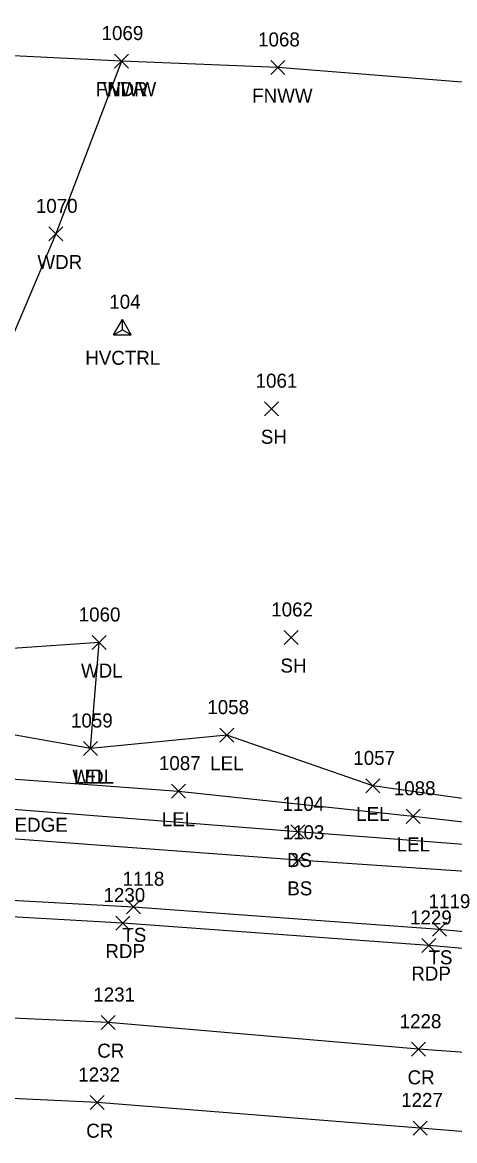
# Model space of a CAD drawing. Extents: x 1629176 to 1637209, y 606063 to 610167.
# Drawn here: x 1629302.4 to 1629364, y 607056.5 to 607215.9 of the extents above; entities that cross this region are included whole.
import ezdxf

# ---------------------------------------------------------------- set-up
doc = ezdxf.new("R2010")
doc.units = 0
for name, color, linetype in [('C_A', 7, 'Continuous'), ('C_C', 7, 'Continuous'), ('C_I', 7, 'Continuous'), ('CPSM', 7, 'Continuous'), ('L_A', 7, 'Continuous'), ('L_I', 7, 'Continuous'), ('L_TIC', 7, 'Continuous'), ('LARO', 7, 'Continuous'), ('LAWA', 7, 'Continuous'), ('LELB', 7, 'Continuous'), ('LFNC', 7, 'Continuous'), ('P_A', 7, 'Continuous'), ('P_I', 7, 'Continuous'), ('P_TIC', 7, 'Continuous'), ('PET', 7, 'Continuous'), ('PRC', 7, 'Continuous')]:
    doc.layers.add(name, color=color, linetype=linetype)

msp = doc.modelspace()

# ---------------------------------------------------------------- linework, layer by layer
at = {"layer": 'CPSM'}
for p, q in [((1629315.4, 607171.35), (1629316.65, 607173.51)), ((1629317.9, 607171.35), (1629316.65, 607173.51)), ((1629316.65, 607172.07), (1629316.65, 607173.51)), ((1629315.4, 607171.35), (1629316.65, 607172.07)), ((1629315.4, 607171.35), (1629317.9, 607171.35)), ((1629316.65, 607172.07), (1629316.65, 607172.07)), ((1629316.65, 607172.07), (1629317.9, 607171.35))]:
    msp.add_line(p, q, dxfattribs=at)
at = {"layer": 'L_TIC'}
for points in [[(1629315.51, 607209.37), (1629317.51, 607211.37)], [(1629317.51, 607209.37), (1629315.51, 607211.37)], [(1629315.51, 607209.37), (1629317.51, 607211.37)], [(1629317.51, 607209.37), (1629315.51, 607211.37)], [(1629337.82, 607208.46), (1629339.82, 607210.46)], [(1629339.82, 607208.46), (1629337.82, 607210.46)], [(1629306.16, 607184.73), (1629308.16, 607186.73)], [(1629308.16, 607184.73), (1629306.16, 607186.73)], [(1629336.9, 607159.81), (1629338.9, 607161.81)], [(1629338.9, 607159.81), (1629336.9, 607161.81)], [(1629312.32, 607126.48), (1629314.32, 607128.48)], [(1629314.32, 607126.48), (1629312.32, 607128.48)], [(1629339.7, 607127.19), (1629341.7, 607129.19)], [(1629341.7, 607127.19), (1629339.7, 607129.19)], [(1629330.53, 607113.27), (1629332.53, 607115.27)], [(1629332.53, 607113.27), (1629330.53, 607115.27)], [(1629311.1, 607111.36), (1629313.1, 607113.36)], [(1629313.1, 607111.36), (1629311.1, 607113.36)], [(1629311.1, 607111.36), (1629313.1, 607113.36)], [(1629313.1, 607111.36), (1629311.1, 607113.36)], [(1629323.64, 607105.29), (1629325.64, 607107.29)], [(1629325.64, 607105.29), (1629323.64, 607107.29)], [(1629351.35, 607106.03), (1629353.35, 607108.03)], [(1629353.35, 607106.03), (1629351.35, 607108.03)], [(1629357.13, 607101.7), (1629359.13, 607103.7)], [(1629359.13, 607101.7), (1629357.13, 607103.7)], [(1629340.68, 607099.48), (1629342.68, 607101.48)], [(1629342.68, 607099.48), (1629340.68, 607101.48)], [(1629340.71, 607095.43), (1629342.71, 607097.43)], [(1629342.71, 607095.43), (1629340.71, 607097.43)], [(1629317.24, 607088.8), (1629319.24, 607090.8)], [(1629319.24, 607088.8), (1629317.24, 607090.8)], [(1629360.89, 607085.6), (1629362.89, 607087.6)], [(1629362.89, 607085.6), (1629360.89, 607087.6)]]:
    msp.add_lwpolyline(points, dxfattribs=at)
at = {"layer": 'LARO'}
msp.add_lwpolyline([(1629525.56, 607097.75), (1629515.16, 607097.62), (1629496.01, 607097.55), (1629454.84, 607100.2), (1629419.24, 607105.4), (1629419.23, 607105.4), (1629378.86, 607107.73), (1629367.09, 607104.98), (1629352.35, 607107.03), (1629331.53, 607114.27), (1629312.1, 607112.36), (1629284.4, 607117.27), (1629264.96, 607112.44), (1629237.03, 607114.71), (1629236.02, 607111.12), (1629264.43, 607110.11), (1629291.77, 607108.71), (1629324.64, 607106.29), (1629358.13, 607102.7), (1629389.76, 607099.17), (1629430.17, 607097.09), (1629468.65, 607094.42), (1629506.63, 607093.09)], dxfattribs=at)
at = {"layer": 'LAWA'}
for points in [[(1629316.51, 607210.37), (1629307.16, 607185.73), (1629298.62, 607165.66), (1629261.38, 607160.41), (1629253.01, 607164.91), (1629257.91, 607184.79), (1629269.2, 607213.11)], [(1629312.1, 607112.36), (1629313.32, 607127.48), (1629283.07, 607125.37), (1629264.34, 607119.92), (1629237.03, 607114.71)]]:
    msp.add_lwpolyline(points, dxfattribs=at)
at = {"layer": 'LELB'}
for points in [[(1629624.92, 607174.61), (1629622.69, 607143.68), (1629611.35, 607114.32), (1629581.53, 607116.51), (1629566.42, 607115.03), (1629550.74, 607095.26), (1629545.75, 607082.85), (1629510.01, 607084.74), (1629471.96, 607087.97), (1629425.24, 607093.21), (1629387.71, 607096.98), (1629341.68, 607100.48), (1629296.79, 607103.99), (1629252.13, 607105.67), (1629240.26, 607107.21), (1629209.02, 607107.58), (1629183.53, 607109.94)], [(1629683.15, 607057.43), (1629646, 607061.54), (1629600.81, 607070.68), (1629551.82, 607076.32), (1629509.64, 607081.4), (1629471.16, 607085.48), (1629425.18, 607090.24), (1629387.34, 607093.37), (1629341.71, 607096.43), (1629295.02, 607099.94), (1629251.22, 607103.28), (1629239.88, 607103.86), (1629208.74, 607106), (1629183.2, 607107.98)], [(1629182.81, 607095.71), (1629228.31, 607094.18), (1629271.2, 607092.37), (1629318.24, 607089.8), (1629361.89, 607086.6), (1629408.03, 607082.19), (1629449.64, 607077.67), (1629495.68, 607072.1), (1629543.77, 607066.01), (1629589.78, 607058.79)]]:
    msp.add_lwpolyline(points, dxfattribs=at)
at = {"layer": 'LFNC'}
msp.add_lwpolyline([(1629584.57, 607180.8), (1629561.91, 607184.66), (1629527.04, 607188.99), (1629501.6, 607191.75), (1629445.35, 607199.37), (1629407.21, 607203.61), (1629374.06, 607206.64), (1629338.82, 607209.46), (1629316.51, 607210.37), (1629282.73, 607212.04), (1629269.2, 607213.11), (1629248.99, 607214.08), (1629210.8, 607215.89), (1629190.17, 607214.66)], dxfattribs=at)
at = {"layer": 'P_TIC'}
for points in [[(1629315.73, 607086.48), (1629317.73, 607088.48)], [(1629317.73, 607086.48), (1629315.73, 607088.48)], [(1629359.37, 607083.28), (1629361.37, 607085.28)], [(1629361.37, 607083.28), (1629359.37, 607085.28)], [(1629313.63, 607072.29), (1629315.63, 607074.29)], [(1629315.63, 607072.29), (1629313.63, 607074.29)], [(1629357.89, 607068.49), (1629359.89, 607070.49)], [(1629359.89, 607068.49), (1629357.89, 607070.49)], [(1629312.06, 607060.88), (1629314.06, 607062.88)], [(1629314.06, 607060.88), (1629312.06, 607062.88)], [(1629358.1, 607057.26), (1629360.1, 607059.26)], [(1629360.1, 607057.26), (1629358.1, 607059.26)]]:
    msp.add_lwpolyline(points, dxfattribs=at)
at = {"layer": 'PET'}
msp.add_lwpolyline([(1630115.59, 606918.47), (1630070.26, 606934.37), (1630047.19, 606942.61), (1630027.81, 606949.5), (1629999.64, 606958.79), (1629963.88, 606969.73), (1629916.37, 606983.66), (1629883.8, 606991.87), (1629841.7, 607003.38), (1629794.53, 607014.94), (1629751.13, 607024.85), (1629703.98, 607035.26), (1629666.74, 607043.02), (1629621.43, 607051.04), (1629588.28, 607056.93), (1629542.89, 607063.67), (1629493.94, 607070.34), (1629447.94, 607075.86), (1629406.53, 607080.22), (1629360.37, 607084.28), (1629316.73, 607087.48), (1629269.81, 607090.12), (1629227.29, 607092.24), (1629182.92, 607093.47)], dxfattribs=at)
at = {"layer": 'PRC'}
for points in [[(1630110.18, 606905.77), (1630065.36, 606921.68), (1630022.36, 606935.68), (1629994.71, 606945.36), (1629959.54, 606955.86), (1629913.54, 606969.37), (1629877.41, 606979.26), (1629837.69, 606989.99), (1629791.63, 607000.82), (1629746.42, 607011.44), (1629699.59, 607021.37), (1629664.04, 607028.34), (1629619.43, 607036.79), (1629585.72, 607042.18), (1629539.96, 607049.3), (1629491.45, 607056.02), (1629445.88, 607061.28), (1629404.36, 607066.23), (1629358.89, 607069.49), (1629314.63, 607073.29), (1629269.37, 607075.36), (1629226.58, 607077.32), (1629182.35, 607078.58)], [(1630105.99, 606894.95), (1630061.18, 606910.94), (1630017.61, 606925.74), (1629991.01, 606934.32), (1629955.3, 606944.84), (1629910.77, 606959.12), (1629874.52, 606969.06), (1629834.93, 606979.4), (1629788.74, 606990.13), (1629743.3, 607000.68), (1629697.98, 607010.33), (1629662.17, 607017.56), (1629618.2, 607025.81), (1629583.59, 607031.56), (1629540.4, 607037.95), (1629489.63, 607045.02), (1629444.26, 607050.14), (1629402.79, 607054.66), (1629359.1, 607058.26), (1629313.06, 607061.88), (1629268.47, 607063.97), (1629226.23, 607065.89), (1629182.22, 607066.96)]]:
    msp.add_lwpolyline(points, dxfattribs=at)

# ---------------------------------------------------------------- texts
at = {"layer": 'C_A'}
msp.add_text('HVCTRL', height=2, dxfattribs=at).set_placement((1629311.35, 607167.07))
at = {"layer": 'C_C'}
msp.add_text('TIE DIST IS 29.685 IS NAIL IN LEDGE', height=2, dxfattribs=at).set_placement((1629262.48, 607100.49))
at = {"layer": 'C_I'}
msp.add_text('104', height=2, dxfattribs=at).set_placement((1629314.78, 607175.07))
at = {"layer": 'L_A'}
for s, p in [('FNWW', (1629312.85, 607205.37)), ('WDR', (1629313.87, 607205.37)), ('FNWW', (1629335.16, 607204.46)), ('WDR', (1629304.53, 607180.73)), ('SH', (1629336.39, 607155.81)), ('WDL', (1629310.74, 607122.48)), ('SH', (1629339.19, 607123.19)), ('LEL', (1629329.17, 607109.27)), ('WDL', (1629309.52, 607107.36)), ('LEL', (1629309.74, 607107.36)), ('LEL', (1629349.99, 607102.03)), ('LEL', (1629322.27, 607101.29)), ('LEL', (1629355.76, 607097.7)), ('BS', (1629340.12, 607095.48)), ('BS', (1629340.16, 607091.43)), ('TS', (1629316.65, 607084.8)), ('TS', (1629360.3, 607081.6))]:
    msp.add_text(s, height=2, dxfattribs=at).set_placement(p)
at = {"layer": 'L_I'}
for s, p in [('1069', (1629313.68, 607213.37)), ('1069', (1629313.68, 607213.37)), ('1068', (1629336, 607212.46)), ('1070', (1629304.31, 607188.73)), ('1061', (1629335.65, 607163.81)), ('1060', (1629310.42, 607130.48)), ('1062', (1629337.88, 607131.19)), ('1058', (1629328.76, 607117.27)), ('1059', (1629309.32, 607115.36)), ('1059', (1629309.32, 607115.36)), ('1057', (1629349.58, 607110.03)), ('1087', (1629321.86, 607109.29)), ('1088', (1629355.35, 607105.7)), ('1104', (1629339.47, 607103.48)), ('1103', (1629339.51, 607099.43)), ('1118', (1629316.68, 607092.8)), ('1119', (1629360.32, 607089.6))]:
    msp.add_text(s, height=2, dxfattribs=at).set_placement(p)
at = {"layer": 'P_A'}
for s, p in [('RDP', (1629314.22, 607082.48)), ('RDP', (1629357.85, 607079.28)), ('CR', (1629313.06, 607068.29)), ('CR', (1629357.32, 607064.49)), ('CR', (1629311.49, 607056.88))]:
    msp.add_text(s, height=2, dxfattribs=at).set_placement(p)
at = {"layer": 'P_I'}
for s, p in [('1230', (1629313.95, 607090.48)), ('1229', (1629357.67, 607087.28)), ('1231', (1629312.5, 607076.29)), ('1228', (1629356.19, 607072.49)), ('1232', (1629310.36, 607064.88)), ('1227', (1629356.4, 607061.26))]:
    msp.add_text(s, height=2, dxfattribs=at).set_placement(p)

doc.saveas('drawing.dxf')
